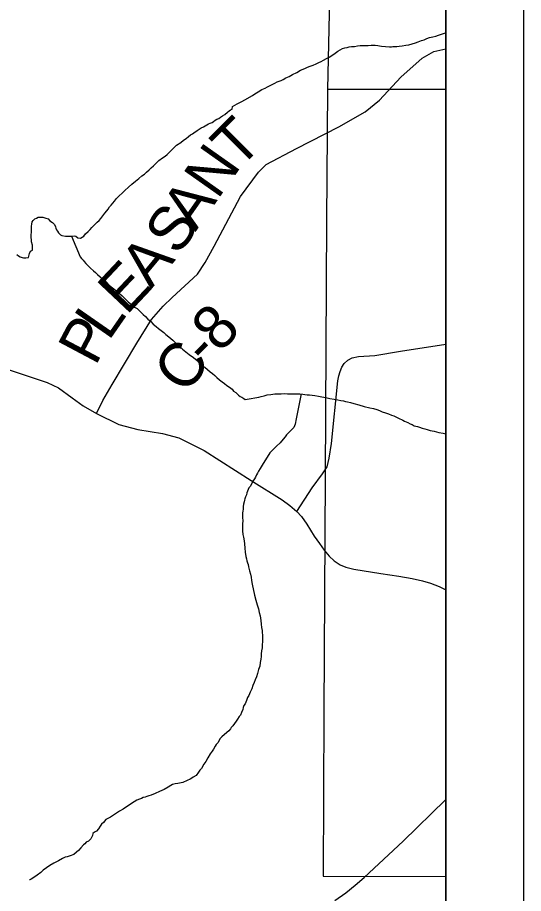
# Model space of a CAD drawing. Extents: x -14196 to 143, y -6096 to 28.
# Drawn here: x 64.351 to 65.003, y 19.711 to 20.839 of the extents above; entities that cross this region are included whole.
import ezdxf

# ---------------------------------------------------------------- set-up
doc = ezdxf.new("R2010")
doc.units = 0
for name, color, linetype in [('GM_X_Corporation', 7, 'Continuous'), ('GM_X_County_Road', 7, 'Continuous'), ('GM_X_County_Road_Text', 7, 'Continuous'), ('GM_X_Minor_River', 7, 'Continuous'), ('GM_X_State_Route', 7, 'Continuous'), ('GM_X_Township_Road', 7, 'Continuous'), ('SH_Data', 7, 'Continuous')]:
    doc.layers.add(name, color=color, linetype=linetype)

msp = doc.modelspace()

# ---------------------------------------------------------------- linework, layer by layer
at = {"layer": 'GM_X_Corporation'}
msp.add_lwpolyline([(64.9028, 18.7286), (64.9028, 23.6985), (58.1028, 23.6985), (58.1028, 18.8711)], dxfattribs=at)
for points in [[(64.9028, 18.7286), (64.9028, 23.6985), (62.6174, 23.6985), (62.6129, 23.4358), (62.306, 23.4402), (62.2824, 22.5866), (62.2815, 22.5484), (62.2751, 22.2884), (62.2487, 21.1358), (62.2323, 20.4208), (62.2235, 19.866), (62.1999, 18.7816), (62.384, 18.775), (62.5403, 18.7731), (63.0887, 18.7577), (63.6879, 18.7414), (64.3696, 18.7343), (64.4266, 18.7347)], [(64.9028, 20.746), (64.9028, 21.2504), (64.8847, 21.2509), (64.76, 21.2549), (64.7538, 20.9025), (64.7504, 20.7466)], [(64.9028, 19.7333), (64.9028, 20.746), (64.7504, 20.7466), (64.7494, 20.5779), (64.7473, 20.248), (64.7458, 19.9449), (64.7449, 19.7339)]]:
    msp.add_lwpolyline(points, close=True, dxfattribs=at)
at = {"layer": 'GM_X_County_Road'}
for points in [[(64.4529, 20.3289), (64.4614, 20.346), (64.4732, 20.3666), (64.505, 20.4196), (64.5237, 20.4501), (64.5389, 20.4673), (64.5505, 20.4782), (64.5832, 20.5083), (64.5932, 20.5235), (64.6047, 20.5443), (64.6387, 20.6081), (64.6615, 20.6396), (64.6716, 20.6493), (64.7105, 20.6699), (64.7649, 20.698), (64.7989, 20.7171), (64.8173, 20.7321), (64.8451, 20.7618), (64.8725, 20.7865), (64.8873, 20.7947), (64.9028, 20.7982)], [(64.3173, 20.3928), (64.3573, 20.3799), (64.3894, 20.369), (64.404, 20.362), (64.4218, 20.3494), (64.436, 20.3389), (64.4529, 20.3289), (64.4817, 20.3151), (64.5062, 20.3085), (64.5379, 20.3032), (64.5591, 20.2979), (64.5915, 20.2814), (64.6524, 20.243), (64.6921, 20.2182), (64.702, 20.2109), (64.7111, 20.2032), (64.7169, 20.1964), (64.724, 20.1865), (64.7335, 20.1713), (64.74, 20.1617), (64.7462, 20.1533), (64.7528, 20.1455), (64.7591, 20.1395), (64.7667, 20.1345), (64.7743, 20.1314), (64.7845, 20.1286), (64.8192, 20.1232), (64.8423, 20.1196), (64.8593, 20.1168), (64.8729, 20.1137), (64.883, 20.1108), (64.8941, 20.1064), (64.9028, 20.1023)]]:
    msp.add_lwpolyline(points, dxfattribs=at)
at = {"layer": 'GM_X_Minor_River'}
for points in [[(64.666, 20.7458), (64.6702, 20.7478), (64.6732, 20.7494), (64.6766, 20.751), (64.6792, 20.7525), (64.6826, 20.7541), (64.6856, 20.7557), (64.6883, 20.7569), (64.6909, 20.7577), (64.6936, 20.7589), (64.6969, 20.7608), (64.7011, 20.7628), (64.7056, 20.7652), (64.7109, 20.7679), (64.7158, 20.771), (64.7214, 20.773), (64.7248, 20.7746), (64.7282, 20.7758), (64.732, 20.7774), (64.7358, 20.779), (64.7392, 20.7806), (64.7422, 20.7822), (64.7452, 20.7837), (64.749, 20.7857), (64.7527, 20.7877), (64.7561, 20.7896), (64.7602, 20.7927), (64.7636, 20.7951), (64.7666, 20.797), (64.77, 20.7986), (64.773, 20.7998), (64.7757, 20.8002), (64.7783, 20.801), (64.7814, 20.8011), (64.7852, 20.8015), (64.789, 20.802), (64.7927, 20.8024), (64.7958, 20.8025), (64.7996, 20.8025), (64.803, 20.8026), (64.8068, 20.803), (64.8098, 20.8031), (64.8117, 20.8031), (64.8152, 20.8024), (64.8175, 20.8021), (64.8201, 20.8017), (64.8304, 20.8008), (64.8327, 20.8008), (64.8346, 20.8012), (64.8372, 20.8013), (64.8399, 20.8013), (64.8429, 20.8017), (64.8467, 20.8022), (64.8513, 20.803), (64.8554, 20.8035), (64.8596, 20.8047), (64.8638, 20.8059), (64.8672, 20.8075), (64.8717, 20.8091), (64.8751, 20.8099), (64.8785, 20.8115), (64.8819, 20.8127), (64.886, 20.8139), (64.8898, 20.8147), (64.8936, 20.8159), (64.8974, 20.8171), (64.9023, 20.8187), (64.9028, 20.8188)], [(64.3696, 20.5703), (64.37, 20.5729), (64.3703, 20.5756), (64.3714, 20.5775), (64.3737, 20.5795), (64.3759, 20.5803), (64.3782, 20.5815), (64.3812, 20.5819), (64.3839, 20.5815), (64.3877, 20.5805), (64.3908, 20.5794), (64.3931, 20.5771), (64.3965, 20.5749), (64.3992, 20.5723), (64.4004, 20.5693), (64.4009, 20.5674), (64.4016, 20.5655), (64.4028, 20.5636), (64.404, 20.5617), (64.4067, 20.5591), (64.4086, 20.558), (64.4132, 20.5573), (64.4174, 20.5574), (64.4216, 20.5574), (64.4246, 20.5575), (64.4265, 20.5571), (64.4292, 20.5553), (64.4326, 20.5546), (64.4368, 20.5573), (64.439, 20.5604), (64.4424, 20.5631), (64.445, 20.5658), (64.4472, 20.5685), (64.4509, 20.5724), (64.4539, 20.5751), (64.4565, 20.5774), (64.4588, 20.5801), (64.4614, 20.5836), (64.464, 20.5867), (64.4662, 20.5898), (64.4681, 20.5921), (64.4699, 20.5948), (64.4718, 20.5971), (64.474, 20.5998), (64.4762, 20.6025), (64.4789, 20.6056), (64.4822, 20.6091), (64.486, 20.6126), (64.4897, 20.6161), (64.4942, 20.6203), (64.4987, 20.6242), (64.5032, 20.6281), (64.5077, 20.6316), (64.5114, 20.6347), (64.5148, 20.6371), (64.5174, 20.6394), (64.5208, 20.6425), (64.5234, 20.6452), (64.5264, 20.6479), (64.5297, 20.651), (64.5335, 20.6545), (64.538, 20.658), (64.5414, 20.6604), (64.544, 20.6623), (64.5462, 20.6646), (64.5559, 20.6743), (64.5616, 20.6778), (64.5653, 20.6806), (64.5687, 20.6829), (64.5717, 20.6856), (64.5743, 20.6876), (64.5766, 20.6891), (64.5785, 20.6903), (64.5826, 20.6934), (64.5852, 20.695), (64.5879, 20.6965), (64.5909, 20.6981), (64.5931, 20.6993), (64.595, 20.7005), (64.5973, 20.7017), (64.5995, 20.7028), (64.6018, 20.7036), (64.6037, 20.7048), (64.6059, 20.7064), (64.6082, 20.7076), (64.6104, 20.7087), (64.6127, 20.7103), (64.6153, 20.7119), (64.6183, 20.7138), (64.6217, 20.7169), (64.624, 20.7185), (64.6258, 20.72), (64.6277, 20.7208), (64.6284, 20.7239), (64.6344, 20.7274), (64.6401, 20.7306), (64.6442, 20.7325), (64.654, 20.7384), (64.657, 20.7404), (64.6611, 20.7431), (64.666, 20.7458)], [(64.3505, 20.5338), (64.3528, 20.5319), (64.3548, 20.5308), (64.3574, 20.5297), (64.3593, 20.5293), (64.362, 20.5294), (64.3654, 20.5298), (64.3668, 20.5348), (64.3683, 20.5379), (64.3706, 20.5391), (64.3709, 20.5429), (64.3708, 20.5455), (64.3696, 20.5501), (64.3692, 20.5527), (64.3691, 20.5554), (64.3691, 20.5573), (64.3691, 20.5592), (64.3694, 20.5619), (64.3694, 20.5645), (64.3693, 20.5665), (64.3696, 20.5703)], [(64.4211, 20.5574), (64.4319, 20.5306), (64.4338, 20.5287), (64.4358, 20.5264), (64.4373, 20.5246), (64.4393, 20.5223), (64.442, 20.5197), (64.4435, 20.5178), (64.4455, 20.5163), (64.4493, 20.5126), (64.4517, 20.5107), (64.4544, 20.5081), (64.4578, 20.5051), (64.4609, 20.5025), (64.4656, 20.4984), (64.4698, 20.4939), (64.4752, 20.4894), (64.4798, 20.486), (64.4829, 20.4834), (64.486, 20.4804), (64.4895, 20.4771), (64.4937, 20.4729), (64.4984, 20.4688), (64.5022, 20.4658), (64.5053, 20.464), (64.513, 20.4565), (64.5161, 20.4539), (64.5192, 20.4505), (64.5231, 20.4475), (64.5262, 20.4442), (64.53, 20.4412), (64.5331, 20.4386), (64.5362, 20.436), (64.5397, 20.4333), (64.5424, 20.4307), (64.5462, 20.4277), (64.5489, 20.4255), (64.5513, 20.4233), (64.5543, 20.4206), (64.5574, 20.418), (64.5601, 20.4154), (64.5636, 20.412), (64.5679, 20.4083), (64.5725, 20.4049), (64.5779, 20.4012), (64.5825, 20.3971), (64.5872, 20.3919), (64.5925, 20.3885), (64.596, 20.3855), (64.5995, 20.3829), (64.6026, 20.3807), (64.6053, 20.3781), (64.608, 20.3755), (64.6115, 20.3725), (64.6149, 20.3699), (64.618, 20.3676), (64.6211, 20.365), (64.6245, 20.3628), (64.6276, 20.3602), (64.6296, 20.3579), (64.6323, 20.3561), (64.6357, 20.3527), (64.6381, 20.3508), (64.64, 20.3501), (64.6427, 20.3482), (64.6446, 20.3471), (64.6469, 20.3475), (64.6522, 20.3484), (64.6571, 20.3492), (64.6597, 20.3497), (64.662, 20.3501), (64.665, 20.3509), (64.6688, 20.3517), (64.673, 20.3529), (64.6775, 20.3534), (64.6825, 20.3542), (64.6867, 20.3543), (64.6908, 20.3544), (64.6946, 20.3548), (64.6988, 20.3545), (64.7049, 20.3546), (64.7087, 20.3543), (64.7121, 20.3543), (64.7148, 20.3544), (64.7186, 20.3541), (64.7213, 20.3534), (64.7243, 20.353), (64.7273, 20.3531), (64.7308, 20.3528), (64.7342, 20.3524), (64.7388, 20.3514), (64.7434, 20.3507), (64.7483, 20.3496), (64.7536, 20.3486), (64.759, 20.3475), (64.764, 20.3465), (64.7678, 20.3458), (64.7712, 20.3454)], [(64.7167, 20.3542), (64.7097, 20.32), (64.7093, 20.3177), (64.709, 20.3154), (64.7072, 20.3112), (64.7038, 20.3077), (64.7012, 20.305), (64.6993, 20.3035), (64.6979, 20.3016), (64.696, 20.2992), (64.6934, 20.2961), (64.6897, 20.2915), (64.6848, 20.2869), (64.6799, 20.2822), (64.6762, 20.2783), (64.6662, 20.2626), (64.6636, 20.2583), (64.6618, 20.2549), (64.6603, 20.2522), (64.6592, 20.2503), (64.6578, 20.2472), (64.6563, 20.2449), (64.6544, 20.2422), (64.653, 20.2391), (64.6511, 20.2353), (64.6493, 20.2333), (64.6485, 20.2314), (64.6467, 20.2272), (64.646, 20.2245), (64.6449, 20.2218), (64.6442, 20.2195), (64.6435, 20.2176), (64.6431, 20.2153), (64.6424, 20.2126), (64.6421, 20.2096), (64.6418, 20.2062), (64.6414, 20.2035), (64.6411, 20.2012), (64.6412, 20.1978), (64.6412, 20.1947), (64.6413, 20.1913), (64.641, 20.1867), (64.6411, 20.1818), (64.6411, 20.178), (64.6416, 20.1734), (64.6424, 20.17), (64.6432, 20.1654), (64.6437, 20.1613), (64.6442, 20.1559), (64.6446, 20.1506), (64.6455, 20.1453), (64.6463, 20.1423), (64.6467, 20.1396), (64.6476, 20.1369), (64.6484, 20.1347), (64.6488, 20.1316), (64.65, 20.1267), (64.6512, 20.1222), (64.6521, 20.1184), (64.6525, 20.1142), (64.6534, 20.1096), (64.6567, 20.0952), (64.6583, 20.0891), (64.6599, 20.0831), (64.6615, 20.0778), (64.6627, 20.0732), (64.6636, 20.0687), (64.6645, 20.0626), (64.6653, 20.058), (64.6657, 20.0539), (64.6662, 20.05), (64.6662, 20.047), (64.6667, 20.0443), (64.6667, 20.0405), (64.6668, 20.0356), (64.6665, 20.0314), (64.6662, 20.0276), (64.6655, 20.0238), (64.6652, 20.0199), (64.6649, 20.0165), (64.6646, 20.0131), (64.6639, 20.0089), (64.6632, 20.0039), (64.6618, 19.9997), (64.6603, 19.9947), (64.6589, 19.9901), (64.6574, 19.9863), (64.656, 19.9829), (64.6545, 19.979), (64.6531, 19.9748), (64.6509, 19.9706), (64.6491, 19.9664), (64.6476, 19.9637), (64.6461, 19.9598), (64.6443, 19.9556), (64.6428, 19.9533)], [(64.7712, 20.3454), (64.7735, 20.3447), (64.7762, 20.344), (64.78, 20.3433), (64.7846, 20.3418), (64.791, 20.3401), (64.7979, 20.3379), (64.8048, 20.3365), (64.8098, 20.3354), (64.814, 20.3343), (64.8174, 20.3329), (64.8208, 20.3314), (64.8251, 20.33), (64.8289, 20.3285), (64.8327, 20.327), (64.8358, 20.3259), (64.8438, 20.3223), (64.8457, 20.3215), (64.8476, 20.3204), (64.8496, 20.3193), (64.8519, 20.3182), (64.8538, 20.3175), (64.8569, 20.316), (64.8595, 20.3149), (64.8622, 20.3134), (64.8664, 20.3124), (64.8691, 20.3113), (64.8722, 20.3102), (64.8756, 20.3095), (64.8786, 20.3084), (64.8828, 20.3073), (64.8878, 20.3063), (64.8939, 20.3048), (64.8993, 20.3038), (64.9028, 20.3031)], [(64.6428, 19.9533), (64.6421, 19.9506), (64.6414, 19.9483), (64.6399, 19.9445), (64.6385, 19.941), (64.6366, 19.9391), (64.6348, 19.936), (64.6329, 19.9333), (64.6307, 19.9303), (64.6288, 19.9272), (64.6266, 19.9252), (64.6255, 19.9233), (64.6236, 19.9206), (64.621, 19.9187), (64.6146, 19.9132), (64.612, 19.9105), (64.6109, 19.9082), (64.6091, 19.9055), (64.6072, 19.9032), (64.6057, 19.9009), (64.6039, 19.8974), (64.6021, 19.8944), (64.5995, 19.8913), (64.5965, 19.8859), (64.5939, 19.8813), (64.5913, 19.8778), (64.5884, 19.8724), (64.5861, 19.8701), (64.5843, 19.8674), (64.5813, 19.8635), (64.5776, 19.8612), (64.5757, 19.86), (64.5738, 19.8585), (64.5697, 19.8569), (64.5644, 19.8545), (64.5579, 19.8532), (64.5542, 19.8524), (64.5511, 19.8516), (64.5489, 19.8504), (64.5455, 19.8481), (64.5402, 19.8453), (64.5342, 19.8429), (64.5285, 19.8402), (64.5236, 19.8382), (64.5206, 19.837), (64.5179, 19.8362), (64.5157, 19.8354), (64.513, 19.835), (64.5111, 19.8338), (64.5085, 19.833), (64.5051, 19.8314), (64.5017, 19.8295), (64.4916, 19.8232), (64.4874, 19.8201), (64.4826, 19.8173), (64.4788, 19.815), (64.475, 19.8123), (64.4713, 19.8099), (64.4675, 19.8079), (64.4649, 19.8068), (64.4619, 19.8029), (64.4597, 19.8006), (64.4578, 19.7979), (64.4556, 19.7948), (64.453, 19.7917), (64.4507, 19.7905), (64.4485, 19.7886), (64.4481, 19.7863), (64.4456, 19.7817), (64.4426, 19.7786), (64.4399, 19.7774), (64.4381, 19.7755), (64.4362, 19.7743), (64.4328, 19.7704), (64.4299, 19.7666), (64.4272, 19.7646), (64.4239, 19.7615), (64.4193, 19.7599), (64.4152, 19.7587), (64.4129, 19.7583), (64.4095, 19.7563), (64.4042, 19.7536), (64.3982, 19.7504), (64.393, 19.7473), (64.3843, 19.7414), (64.3813, 19.7387), (64.3768, 19.7352), (64.3723, 19.7321), (64.3689, 19.7301), (64.3671, 19.7289), (64.3671, 19.7289), (64.3667, 19.7289)]]:
    msp.add_lwpolyline(points, dxfattribs=at)
at = {"layer": 'GM_X_State_Route'}
msp.add_lwpolyline([(64.7599, 19.7026), (64.774, 19.7125), (64.7862, 19.7222), (64.7977, 19.7322), (64.8477, 19.7789), (64.9025, 19.8322), (64.9028, 19.8325)], dxfattribs=at)
at = {"layer": 'GM_X_Township_Road'}
msp.add_lwpolyline([(64.7111, 20.2032), (64.7308, 20.2333), (64.7442, 20.2516), (64.7499, 20.2605), (64.7526, 20.2715), (64.7557, 20.2906), (64.764, 20.3712), (64.7651, 20.3776), (64.7667, 20.3833), (64.7688, 20.3887), (64.7719, 20.3934), (64.7767, 20.3976), (64.7824, 20.4006), (64.7902, 20.4025), (64.8115, 20.4039), (64.8443, 20.4095), (64.9028, 20.4181)], dxfattribs=at)
at = {"layer": 'SH_Data'}
for p, q in [((65.0028, 23.7985), (65.0028, 16.7985)), ((64.9028, 23.6985), (64.9028, 16.8985))]:
    msp.add_line(p, q, dxfattribs=at)

# ---------------------------------------------------------------- texts
at = {"layer": 'GM_X_County_Road_Text'}
for s, rotation, p in [('T', 44.9879, (64.6361, 20.6421)), ('N', 54.7922, (64.6089, 20.6033)), ('A', 55.1104, (64.5804, 20.5623)), ('S', 54.9278, (64.5582, 20.5308)), ('A', 50.2298, (64.5232, 20.4883)), ('E', 46.6882, (64.4915, 20.4545)), ('L', 55.233, (64.4686, 20.4213)), ('8', 47.1335, (64.6121, 20.4058)), ('P', 62.0706, (64.4516, 20.389)), ('C', 53.7663, (64.5687, 20.352)), ('-', 45.8666, (64.5949, 20.3881))]:
    msp.add_text(s, height=0.0568, rotation=rotation, dxfattribs=at).set_placement(p)

doc.saveas('drawing.dxf')
